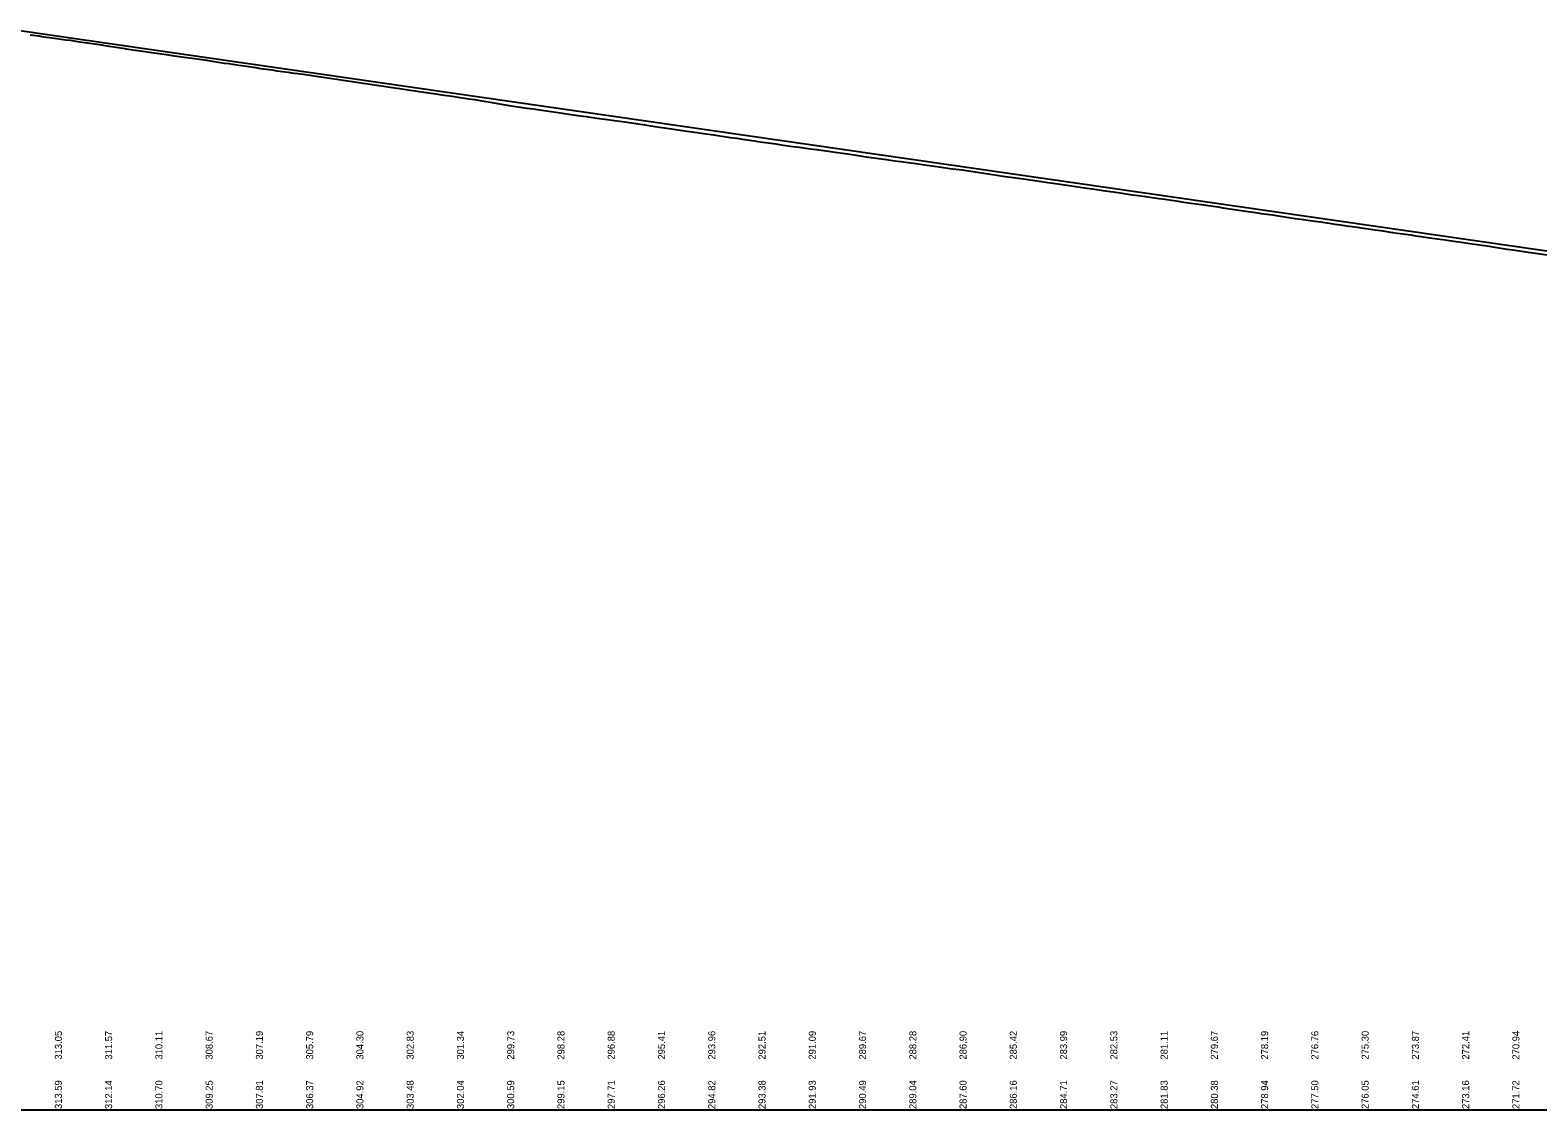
# Model space of a CAD drawing. Extents: x 1876258 to 1926563, y 729739 to 834437.
# Drawn here: x 1892831 to 1894330, y 827963 to 829037 of the extents above; entities that cross this region are included whole.
import ezdxf

# ---------------------------------------------------------------- set-up
doc = ezdxf.new("R2010")
doc.units = 0
for name, color, linetype in [('RD_EX_BldgApp', 7, 'Continuous'), ('RD_EX_RailRoad', 7, 'Continuous'), ('RD_PD_ALT5_CL', 7, 'Continuous'), ('RD_PD_Final_Cl', 7, 'Continuous')]:
    doc.layers.add(name, color=color, linetype=linetype)

msp = doc.modelspace()

# ---------------------------------------------------------------- linework, layer by layer
at = {"layer": 'RD_EX_BldgApp'}
for points in [[(1892830.4, 829032.5), (1892833.4, 829032.1), (1892838.7, 829031.4), (1892843.7, 829030.7), (1892852.1, 829029.5), (1892857.1, 829028.8), (1892865.8, 829027.7), (1892870.2, 829027.1), (1892879.5, 829025.6), (1892884.8, 829024.8), (1892894.4, 829023.5), (1892899.2, 829022.8), (1892908.9, 829021.3), (1892913.9, 829020.5), (1892924.9, 829018.9), (1892926, 829018.7), (1892935, 829017.4), (1892940.2, 829016.7), (1892951.2, 829015.1), (1892956.2, 829014.3), (1892966.3, 829012.9), (1892971.9, 829012.1), (1892983.7, 829010.4), (1892989.1, 829009.7), (1892994.5, 829008.9), (1893006.2, 829007.2), (1893011.6, 829006.4), (1893023.8, 829004.5), (1893028.1, 829003.9), (1893038.3, 829002.5), (1893043.4, 829001.7), (1893055.1, 828999.9), (1893059.8, 828999.2), (1893071.4, 828997.6), (1893076, 828996.9), (1893087.1, 828995.3), (1893090.4, 828994.7), (1893099.7, 828993.6), (1893104.4, 828993), (1893115.1, 828991.4), (1893120.1, 828990.7), (1893130.6, 828989.2), (1893135.6, 828988.5), (1893146.1, 828986.9), (1893151.2, 828986.1), (1893161.7, 828984.5), (1893166.7, 828983.8), (1893177.4, 828982.3), (1893182.5, 828981.5), (1893193.1, 828979.9)], [(1893193.1, 828979.9), (1893198.2, 828979.1), (1893208.5, 828977.6), (1893213.4, 828976.9), (1893217.4, 828976.3), (1893229.4, 828974.5), (1893234, 828973.8), (1893239.8, 828973), (1893250.5, 828971.4), (1893256.2, 828970.5), (1893267.1, 828968.9), (1893272.5, 828968.1), (1893278.1, 828967.2), (1893290, 828965.1), (1893295.5, 828964.3), (1893307, 828962.4), (1893313.8, 828961.3), (1893324.9, 828959.6), (1893330.9, 828958.8), (1893342, 828957.3), (1893349, 828956.2), (1893358.3, 828954.9), (1893370.9, 828953.1), (1893377.6, 828952.1), (1893383.9, 828951.3), (1893394.4, 828949.7), (1893404.8, 828948.3), (1893411.8, 828947.4), (1893422, 828945.9), (1893428.8, 828944.9), (1893440.1, 828943.3), (1893445.9, 828942.4), (1893456.6, 828940.8), (1893463.9, 828939.7), (1893475.3, 828938.1), (1893481.6, 828937.1), (1893494.1, 828935.3), (1893500.3, 828934.4), (1893510.7, 828932.9), (1893516.5, 828932.1), (1893527.3, 828930.5), (1893533.5, 828929.6), (1893539.2, 828928.8), (1893550.8, 828927.1), (1893556.8, 828926.2), (1893567.4, 828924.7), (1893569.7, 828924.4), (1893572.2, 828924), (1893577.5, 828923.2), (1893589.3, 828921.6), (1893595.9, 828920.7), (1893606.4, 828919.2), (1893612.7, 828918.3), (1893624.8, 828916.7), (1893631.4, 828915.8), (1893643.5, 828914), (1893650.4, 828913), (1893662.2, 828911.3), (1893669.7, 828910.2), (1893682.4, 828908.4), (1893690.7, 828907.3), (1893696.7, 828906.5), (1893706.5, 828905.1), (1893712.1, 828904.4), (1893720.3, 828903.2), (1893725.2, 828902.5), (1893737.3, 828900.8), (1893745.3, 828899.7), (1893757.7, 828898.1), (1893764.5, 828897.1), (1893776.8, 828895.3), (1893783.8, 828894.3), (1893796.1, 828892.4), (1893803, 828891.4), (1893808.9, 828890.5), (1893821, 828888.8), (1893827.7, 828887.9), (1893840.8, 828886), (1893842.5, 828885.7), (1893848.2, 828884.8), (1893859.8, 828883.2), (1893870.9, 828881.6), (1893879.4, 828880.4), (1893889.6, 828878.9), (1893895.9, 828877.9), (1893897.8, 828877.7), (1893907.9, 828876.2), (1893914.8, 828875.2), (1893927, 828873.5), (1893933.1, 828872.7), (1893940, 828871.7), (1893953.7, 828869.7), (1893959.2, 828868.9), (1893972.5, 828867), (1893978, 828866.2), (1893990.6, 828864.4), (1893995.8, 828863.7), (1894012, 828861.3), (1894017.2, 828860.5), (1894030.8, 828858.5), (1894035.3, 828857.8)], [(1894035.3, 828857.8), (1894051.7, 828855.4), (1894054.9, 828854.9), (1894057.8, 828854.5), (1894066.5, 828853.3), (1894072.5, 828852.4), (1894089.1, 828849.9), (1894095.1, 828849.1), (1894108.5, 828847.3), (1894114.4, 828846.4), (1894128.8, 828844.3), (1894134.1, 828843.5), (1894140.3, 828842.6), (1894151.1, 828841.1), (1894157, 828840.2), (1894168.6, 828838.5), (1894174.3, 828837.7), (1894185.7, 828835.9), (1894190.8, 828835.2), (1894204.2, 828833.4), (1894209.1, 828832.7), (1894216.3, 828831.7), (1894220.6, 828831), (1894230.3, 828829.5), (1894236, 828828.8), (1894249.1, 828826.8), (1894254.2, 828826.1), (1894265, 828824.6), (1894270.2, 828823.8), (1894282.1, 828822.1), (1894287.7, 828821.2), (1894300, 828819.4), (1894305.4, 828818.6), (1894320.9, 828816.4), (1894325.7, 828815.7), (1894339.7, 828813.8)]]:
    msp.add_lwpolyline(points, dxfattribs=at)
at = {"layer": 'RD_PD_ALT5_CL'}
msp.add_line((1892818.1, 829037.2), (1894783.1, 828753.6), dxfattribs=at)
at = {"layer": 'RD_PD_Final_Cl'}
msp.add_line((1878363.1, 827962.8), (1926563.1, 827962.8), dxfattribs=at)

# ---------------------------------------------------------------- texts
at = {"layer": 'RD_EX_RailRoad'}
for s, p in [('313.05', (1892862.1, 828012.8)), ('311.57', (1892912.1, 828012.8)), ('310.11', (1892962.1, 828012.8)), ('308.67', (1893012.1, 828012.8)), ('307.19', (1893062.1, 828012.8)), ('305.79', (1893112.1, 828012.8)), ('304.30', (1893162.1, 828012.8)), ('302.83', (1893212.1, 828012.8)), ('301.34', (1893262.1, 828012.8)), ('299.73', (1893312.1, 828012.8)), ('298.28', (1893362.1, 828012.8)), ('296.88', (1893412.1, 828012.8)), ('295.41', (1893462.1, 828012.8)), ('293.96', (1893512.1, 828012.8)), ('292.51', (1893562.1, 828012.8)), ('291.09', (1893612.1, 828012.8)), ('289.67', (1893662.1, 828012.8)), ('288.28', (1893712.1, 828012.8)), ('286.90', (1893762.1, 828012.8)), ('285.42', (1893812.1, 828012.8)), ('283.99', (1893862.1, 828012.8)), ('282.53', (1893912.1, 828012.8)), ('281.11', (1893962.1, 828012.8)), ('279.67', (1894012.1, 828012.8)), ('278.19', (1894062.1, 828012.8)), ('276.76', (1894112.1, 828012.8)), ('275.30', (1894162.1, 828012.8)), ('273.87', (1894212.1, 828012.8)), ('272.41', (1894262.1, 828012.8)), ('270.94', (1894312.1, 828012.8)), ('313.59', (1892862.1, 827963.6)), ('312.14', (1892912.1, 827963.6)), ('310.70', (1892962.1, 827963.6)), ('309.25', (1893012.1, 827963.6)), ('307.81', (1893062.1, 827963.6)), ('306.37', (1893112.1, 827963.6)), ('304.92', (1893162.1, 827963.6)), ('303.48', (1893212.1, 827963.6)), ('302.04', (1893262.1, 827963.6)), ('300.59', (1893312.1, 827963.6)), ('299.15', (1893362.1, 827963.6)), ('297.71', (1893412.1, 827963.6)), ('296.26', (1893462.1, 827963.6)), ('294.82', (1893512.1, 827963.6)), ('293.38', (1893562.1, 827963.6)), ('291.93', (1893612.1, 827963.6)), ('290.49', (1893662.1, 827963.6)), ('289.04', (1893712.1, 827963.6)), ('287.60', (1893762.1, 827963.6)), ('286.16', (1893812.1, 827963.6)), ('284.71', (1893862.1, 827963.6)), ('283.27', (1893912.1, 827963.6)), ('281.83', (1893962.1, 827963.6)), ('280.38', (1894012.1, 827963.6)), ('278.94', (1894062.1, 827963.6)), ('277.50', (1894112.1, 827963.6)), ('276.05', (1894162.1, 827963.6)), ('274.61', (1894212.1, 827963.6)), ('273.16', (1894262.1, 827963.6)), ('271.72', (1894312.1, 827963.6))]:
    msp.add_text(s, height=7, rotation=90, dxfattribs=at).set_placement(p)

doc.saveas('drawing.dxf')
